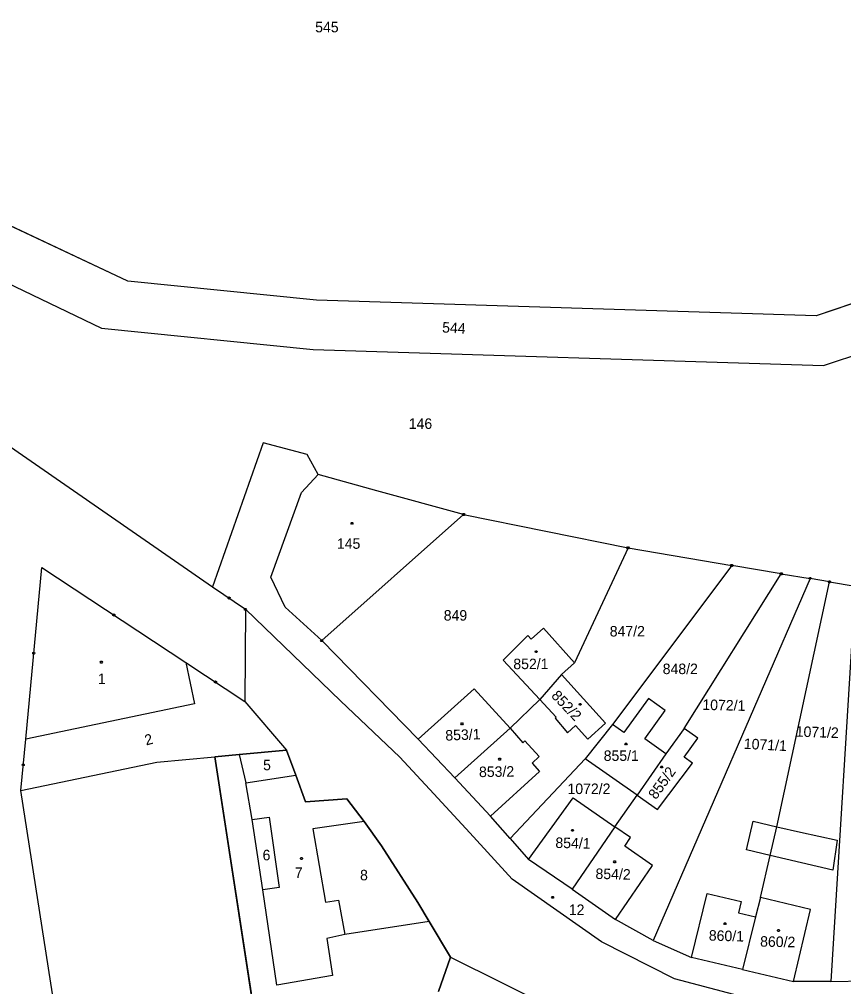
# Model space of a CAD drawing. Extents: x -841286 to -834997, y -1020681 to -1017810.
# Drawn here: x -838876.5 to -838743.2, y -1019133.5 to -1018977 of the extents above; entities that cross this region are included whole.
import ezdxf

# ---------------------------------------------------------------- set-up
doc = ezdxf.new("R2010")
doc.units = 0
for name, color, linetype in [('NERES_HRA', 7, 'Continuous'), ('OVNE_POP', 7, 'Continuous'), ('OVNE_PRE', 7, 'Continuous'), ('OVNE_SET', 7, 'Continuous'), ('OVNI_PRE', 7, 'Continuous'), ('OVNI_SET', 7, 'Continuous')]:
    doc.layers.add(name, color=color, linetype=linetype)

msp = doc.modelspace()

# ---------------------------------------------------------------- linework, layer by layer
at = {"layer": 'NERES_HRA'}
for points in [[(-838804.56, -1019056.95), (-838804.47, -1019057.1), (-838804.56, -1019057.25), (-838804.74, -1019057.25), (-838804.83, -1019057.1), (-838804.74, -1019056.95)], [(-838777.95, -1019062.36), (-838777.86, -1019062.51), (-838777.95, -1019062.66), (-838778.13, -1019062.66), (-838778.22, -1019062.51), (-838778.13, -1019062.36)], [(-838761.17, -1019065.2), (-838761.08, -1019065.35), (-838761.17, -1019065.5), (-838761.35, -1019065.5), (-838761.44, -1019065.35), (-838761.35, -1019065.2)], [(-838753.15, -1019066.57), (-838753.06, -1019066.72), (-838753.15, -1019066.87), (-838753.33, -1019066.87), (-838753.42, -1019066.72), (-838753.33, -1019066.57)], [(-838748.48, -1019067.3), (-838748.39, -1019067.45), (-838748.48, -1019067.6), (-838748.66, -1019067.6), (-838748.75, -1019067.45), (-838748.66, -1019067.3)], [(-838745.35, -1019067.86), (-838745.26, -1019068.01), (-838745.35, -1019068.16), (-838745.53, -1019068.16), (-838745.62, -1019068.01), (-838745.53, -1019067.86)], [(-838839.86, -1019072.3), (-838839.77, -1019072.45), (-838839.86, -1019072.6), (-838840.04, -1019072.6), (-838840.13, -1019072.45), (-838840.04, -1019072.3)], [(-838827.51, -1019077.37), (-838827.42, -1019077.52), (-838827.51, -1019077.67), (-838827.69, -1019077.67), (-838827.78, -1019077.52), (-838827.69, -1019077.37)]]:
    msp.add_lwpolyline(points, close=True, dxfattribs=at)
at = {"layer": 'OVNE_POP'}
for points in [[(-838822.6, -1019058.38), (-838822.51, -1019058.53), (-838822.6, -1019058.68), (-838822.78, -1019058.68), (-838822.87, -1019058.53), (-838822.78, -1019058.38)], [(-838863.18, -1019080.87), (-838863.09, -1019081.02), (-838863.18, -1019081.17), (-838863.36, -1019081.17), (-838863.45, -1019081.02), (-838863.36, -1019080.87)], [(-838790.14, -1019118.92), (-838790.05, -1019119.07), (-838790.14, -1019119.22), (-838790.32, -1019119.22), (-838790.41, -1019119.07), (-838790.32, -1019118.92)]]:
    msp.add_lwpolyline(points, close=True, dxfattribs=at)
at = {"layer": 'OVNE_SET'}
for p, q in [((-838859, -1019019.35), (-838948.75, -1018976.96)), ((-838944.44, -1018987.93), (-838863.24, -1019026.97)), ((-838702.3, -1019009.58), (-838747.6, -1019024.97)), ((-838828.44, -1019022.39), (-838859, -1019019.35)), ((-838746.4, -1019033.01), (-838707.91, -1019019.94)), ((-838747.6, -1019024.97), (-838828.44, -1019022.39)), ((-838908.59, -1019025.03), (-838845.25, -1019068.79)), ((-838863.24, -1019026.97), (-838828.96, -1019030.38)), ((-838828.96, -1019030.38), (-838746.4, -1019033.01)), ((-838837.08, -1019045.49), (-838845.25, -1019068.79)), ((-838829.97, -1019047.4), (-838837.08, -1019045.49)), ((-838828.2, -1019050.62), (-838829.97, -1019047.4)), ((-838830.87, -1019053.56), (-838828.2, -1019050.62)), ((-838818.69, -1019053.29), (-838828.2, -1019050.62)), ((-838835.82, -1019067.23), (-838830.87, -1019053.56)), ((-838804.65, -1019057.1), (-838818.69, -1019053.29)), ((-838827.6, -1019077.52), (-838804.65, -1019057.1)), ((-838804.65, -1019057.1), (-838778.04, -1019062.51)), ((-838778.04, -1019062.51), (-838786.71, -1019081.1)), ((-838778.04, -1019062.51), (-838761.26, -1019065.35)), ((-838761.26, -1019065.35), (-838780.53, -1019091.09)), ((-838753.24, -1019066.72), (-838761.26, -1019065.35)), ((-838875.5, -1019093.46), (-838872.88, -1019065.68)), ((-838872.88, -1019065.68), (-838849.58, -1019081.06)), ((-838768.98, -1019091.73), (-838753.24, -1019066.72)), ((-838753.24, -1019066.72), (-838748.57, -1019067.45)), ((-838833.52, -1019072.1), (-838835.82, -1019067.23)), ((-838748.57, -1019067.45), (-838773.97, -1019126.07)), ((-838753.96, -1019107.64), (-838745.44, -1019068.01)), ((-838745.44, -1019068.01), (-838748.57, -1019067.45)), ((-838745.44, -1019068.01), (-838741.31, -1019068.7)), ((-838741.31, -1019068.7), (-838745.21, -1019132.7)), ((-838845.25, -1019068.79), (-838839.95, -1019072.45)), ((-838839.95, -1019072.45), (-838840.03, -1019087.37)), ((-838824.54, -1019087.29), (-838839.95, -1019072.45)), ((-838827.6, -1019077.52), (-838833.52, -1019072.1)), ((-838791.73, -1019075.52), (-838793.69, -1019077.28)), ((-838786.71, -1019081.1), (-838791.73, -1019075.52)), ((-838812.01, -1019093.46), (-838827.6, -1019077.52)), ((-838798.27, -1019080.68), (-838794.24, -1019076.67)), ((-838793.69, -1019077.28), (-838794.24, -1019076.67)), ((-838849.58, -1019081.06), (-838840.03, -1019087.37)), ((-838849.58, -1019081.06), (-838848.18, -1019087.74)), ((-838792.32, -1019087.07), (-838798.27, -1019080.68)), ((-838788.81, -1019082.99), (-838786.71, -1019081.1)), ((-838788.81, -1019082.99), (-838792.32, -1019087.07)), ((-838781.7, -1019090.89), (-838788.81, -1019082.99)), ((-838812.01, -1019093.46), (-838802.95, -1019085.33)), ((-838802.95, -1019085.33), (-838797.11, -1019091.69)), ((-838840.03, -1019087.37), (-838833.28, -1019095.23)), ((-838814.95, -1019096.39), (-838824.54, -1019087.29)), ((-838792.32, -1019087.07), (-838797.11, -1019091.69)), ((-838792.32, -1019087.07), (-838789.65, -1019089.92)), ((-838774.73, -1019086.89), (-838778.71, -1019092.4)), ((-838772.04, -1019088.83), (-838774.73, -1019086.89)), ((-838848.18, -1019087.74), (-838875.5, -1019093.46)), ((-838775.34, -1019093.41), (-838772.04, -1019088.83)), ((-838789.65, -1019089.92), (-838789.82, -1019090.07)), ((-838789.82, -1019090.07), (-838787.84, -1019092.42)), ((-838797.11, -1019091.69), (-838806.06, -1019099.72)), ((-838797.11, -1019091.69), (-838795.08, -1019094.05)), ((-838787.84, -1019092.42), (-838786.54, -1019091.25)), ((-838786.54, -1019091.25), (-838784.55, -1019093.46)), ((-838780.53, -1019091.09), (-838784.96, -1019096.65)), ((-838784.55, -1019093.46), (-838781.7, -1019090.89)), ((-838778.71, -1019092.4), (-838780.53, -1019091.09)), ((-838768.98, -1019091.73), (-838771.95, -1019095.85)), ((-838766.76, -1019093.33), (-838768.98, -1019091.73)), ((-838876.29, -1019101.79), (-838875.5, -1019093.46)), ((-838806.06, -1019099.72), (-838812.01, -1019093.46)), ((-838795.08, -1019094.05), (-838794.75, -1019093.72)), ((-838794.75, -1019093.72), (-838792.43, -1019096.29)), ((-838771.95, -1019095.85), (-838775.34, -1019093.41)), ((-838768.96, -1019096.38), (-838766.76, -1019093.33)), ((-838840.98, -1019095.94), (-838833.28, -1019095.23)), ((-838833.28, -1019095.23), (-838831.81, -1019099.29)), ((-838854.28, -1019097.19), (-838844.9, -1019096.31)), ((-838844.9, -1019096.31), (-838840.98, -1019095.94)), ((-838838.17, -1019140.12), (-838844.9, -1019096.31)), ((-838840.98, -1019095.94), (-838839.9, -1019100.55)), ((-838809.46, -1019102.3), (-838814.95, -1019096.39)), ((-838784.96, -1019096.65), (-838797.11, -1019109.54)), ((-838792.43, -1019096.29), (-838793.57, -1019097.33)), ((-838776.54, -1019102.53), (-838784.96, -1019096.65)), ((-838771.95, -1019095.85), (-838776.54, -1019102.53)), ((-838767.59, -1019097.37), (-838768.96, -1019096.38)), ((-838876.29, -1019101.79), (-838854.28, -1019097.19)), ((-838793.57, -1019097.33), (-838792.35, -1019098.69)), ((-838773.29, -1019104.84), (-838767.59, -1019097.37)), ((-838839.9, -1019100.55), (-838831.81, -1019099.29)), ((-838831.81, -1019099.29), (-838830.25, -1019103.61)), ((-838800.32, -1019105.96), (-838806.06, -1019099.72)), ((-838792.35, -1019098.69), (-838800.32, -1019105.96)), ((-838838.87, -1019106.47), (-838839.9, -1019100.55)), ((-838862.62, -1019189.07), (-838876.29, -1019101.79)), ((-838830.25, -1019103.61), (-838823.55, -1019103.11)), ((-838823.55, -1019103.11), (-838820.76, -1019106.79)), ((-838803.62, -1019108.65), (-838809.46, -1019102.3)), ((-838794.14, -1019112.95), (-838786.9, -1019102.96)), ((-838786.9, -1019102.96), (-838780.17, -1019107.65)), ((-838780.17, -1019107.65), (-838776.54, -1019102.53)), ((-838776.54, -1019102.53), (-838773.29, -1019104.84)), ((-838838.87, -1019106.47), (-838836.12, -1019106.09)), ((-838836.12, -1019106.09), (-838834.48, -1019117.5)), ((-838797.11, -1019109.54), (-838800.32, -1019105.96)), ((-838837.11, -1019117.84), (-838838.87, -1019106.47)), ((-838820.76, -1019106.79), (-838829.03, -1019107.99)), ((-838820.76, -1019106.79), (-838817.92, -1019110.72)), ((-838780.17, -1019107.65), (-838787.08, -1019117.73)), ((-838777.66, -1019109.4), (-838780.17, -1019107.65)), ((-838755.04, -1019112.3), (-838753.96, -1019107.64)), ((-838829.03, -1019107.99), (-838826.98, -1019119.88)), ((-838796.77, -1019116.14), (-838803.62, -1019108.65)), ((-838778.54, -1019110.78), (-838777.66, -1019109.4)), ((-838817.92, -1019110.72), (-838812.07, -1019119.9)), ((-838797.11, -1019109.54), (-838794.14, -1019112.95)), ((-838774.06, -1019113.94), (-838778.54, -1019110.78)), ((-838756.62, -1019119.1), (-838755.04, -1019112.3)), ((-838787.08, -1019117.73), (-838794.14, -1019112.95)), ((-838780.08, -1019122.65), (-838774.06, -1019113.94)), ((-838782.36, -1019126.28), (-838796.77, -1019116.14)), ((-838834.48, -1019117.5), (-838837.11, -1019117.84)), ((-838834.87, -1019133.27), (-838837.11, -1019117.84)), ((-838787.08, -1019117.73), (-838780.08, -1019122.65)), ((-838767.77, -1019128.8), (-838765.26, -1019118.45)), ((-838765.26, -1019118.45), (-838759.72, -1019119.77)), ((-838826.98, -1019119.88), (-838824.91, -1019119.53)), ((-838824.91, -1019119.53), (-838823.84, -1019125.11)), ((-838812.07, -1019119.9), (-838810.21, -1019123.01)), ((-838759.72, -1019119.77), (-838760.15, -1019121.57)), ((-838756.62, -1019119.1), (-838757.41, -1019122.23)), ((-838748.51, -1019121.03), (-838756.62, -1019119.1)), ((-838760.15, -1019121.57), (-838757.41, -1019122.23)), ((-838751.28, -1019132.69), (-838748.51, -1019121.03)), ((-838810.21, -1019123.01), (-838823.84, -1019125.11)), ((-838810.21, -1019123.01), (-838806.77, -1019128.77)), ((-838773.97, -1019126.07), (-838780.08, -1019122.65)), ((-838757.41, -1019122.23), (-838759.52, -1019130.74)), ((-838823.84, -1019125.11), (-838826.8, -1019125.73)), ((-838826.8, -1019125.73), (-838825.88, -1019131.72)), ((-838770.54, -1019132.25), (-838782.36, -1019126.28)), ((-838773.97, -1019126.07), (-838767.77, -1019128.8)), ((-838806.77, -1019128.77), (-838808.73, -1019134.31)), ((-838806.77, -1019128.77), (-838770.31, -1019146.82)), ((-838759.52, -1019130.74), (-838767.77, -1019128.8)), ((-838759.52, -1019130.74), (-838751.28, -1019132.69)), ((-838825.88, -1019131.72), (-838834.87, -1019133.27)), ((-838760.9, -1019134.8), (-838770.54, -1019132.25)), ((-838745.21, -1019132.7), (-838751.28, -1019132.69)), ((-838745.21, -1019132.7), (-838739.12, -1019132.55))]:
    msp.add_line(p, q, dxfattribs=at)
for points in [[(-838842.44, -1019070.55), (-838842.45, -1019070.72), (-838842.61, -1019070.79), (-838842.76, -1019070.69), (-838842.75, -1019070.52), (-838842.59, -1019070.45)], [(-838861.07, -1019073.29), (-838861.08, -1019073.47), (-838861.24, -1019073.54), (-838861.39, -1019073.45), (-838861.38, -1019073.27), (-838861.22, -1019073.2)], [(-838874.33, -1019079.47), (-838874.17, -1019079.39), (-838874.03, -1019079.49), (-838874.05, -1019079.67), (-838874.21, -1019079.75), (-838874.35, -1019079.65)], [(-838844.65, -1019084.14), (-838844.65, -1019084.31), (-838844.81, -1019084.39), (-838844.96, -1019084.29), (-838844.96, -1019084.12), (-838844.8, -1019084.04)], [(-838876.04, -1019097.52), (-838875.88, -1019097.45), (-838875.74, -1019097.55), (-838875.75, -1019097.73), (-838875.91, -1019097.8), (-838876.05, -1019097.7)]]:
    msp.add_lwpolyline(points, close=True, dxfattribs=at)
at = {"layer": 'OVNI_PRE'}
for points in [[(-838792.82, -1019079.15), (-838792.73, -1019079.3), (-838792.82, -1019079.45), (-838793, -1019079.45), (-838793.09, -1019079.3), (-838793, -1019079.15)], [(-838785.7, -1019087.68), (-838785.61, -1019087.83), (-838785.7, -1019087.98), (-838785.88, -1019087.98), (-838785.97, -1019087.83), (-838785.88, -1019087.68)], [(-838804.81, -1019090.84), (-838804.72, -1019090.99), (-838804.81, -1019091.14), (-838804.99, -1019091.14), (-838805.08, -1019090.99), (-838804.99, -1019090.84)], [(-838778.28, -1019094.1), (-838778.19, -1019094.25), (-838778.28, -1019094.4), (-838778.46, -1019094.4), (-838778.55, -1019094.25), (-838778.46, -1019094.1)], [(-838798.71, -1019096.56), (-838798.62, -1019096.71), (-838798.71, -1019096.86), (-838798.89, -1019096.86), (-838798.98, -1019096.71), (-838798.89, -1019096.56)], [(-838772.52, -1019097.82), (-838772.43, -1019097.97), (-838772.52, -1019098.12), (-838772.7, -1019098.12), (-838772.79, -1019097.97), (-838772.7, -1019097.82)], [(-838786.94, -1019108.07), (-838786.85, -1019108.22), (-838786.94, -1019108.37), (-838787.12, -1019108.37), (-838787.21, -1019108.22), (-838787.12, -1019108.07)], [(-838830.78, -1019112.63), (-838830.69, -1019112.78), (-838830.78, -1019112.93), (-838830.96, -1019112.93), (-838831.05, -1019112.78), (-838830.96, -1019112.63)], [(-838780.1, -1019113.19), (-838780.01, -1019113.34), (-838780.1, -1019113.49), (-838780.28, -1019113.49), (-838780.37, -1019113.34), (-838780.28, -1019113.19)], [(-838762.27, -1019123.18), (-838762.18, -1019123.33), (-838762.27, -1019123.48), (-838762.45, -1019123.48), (-838762.54, -1019123.33), (-838762.45, -1019123.18)], [(-838753.6, -1019124.3), (-838753.51, -1019124.45), (-838753.6, -1019124.6), (-838753.78, -1019124.6), (-838753.87, -1019124.45), (-838753.78, -1019124.3)]]:
    msp.add_lwpolyline(points, close=True, dxfattribs=at)
at = {"layer": 'OVNI_SET'}
for p, q in [((-838758.88, -1019111.37), (-838757.78, -1019106.74)), ((-838757.78, -1019106.74), (-838753.96, -1019107.64)), ((-838753.96, -1019107.64), (-838750.15, -1019108.54)), ((-838750.15, -1019108.54), (-838744.2, -1019109.8)), ((-838744.2, -1019109.8), (-838744.9, -1019114.65)), ((-838755.04, -1019112.3), (-838758.88, -1019111.37)), ((-838744.9, -1019114.65), (-838755.04, -1019112.3))]:
    msp.add_line(p, q, dxfattribs=at)
for points in [[(-838702.3, -1019009.58), (-838747.6, -1019024.97), (-838828.44, -1019022.39), (-838859, -1019019.35), (-838948.75, -1018976.96), (-838956.29, -1018978.9), (-838962.1, -1018986.94)], [(-838808.73, -1019134.31), (-838806.77, -1019128.77), (-838810.21, -1019123.01), (-838812.07, -1019119.9), (-838817.92, -1019110.72), (-838820.76, -1019106.79), (-838823.55, -1019103.11), (-838830.25, -1019103.61), (-838831.81, -1019099.29), (-838833.28, -1019095.23), (-838840.98, -1019095.94), (-838844.9, -1019096.31), (-838838.17, -1019140.12), (-838822.57, -1019164.73)]]:
    msp.add_lwpolyline(points, dxfattribs=at)

# ---------------------------------------------------------------- texts
at = {"layer": 'OVNE_PRE'}
for s, p in [('545', (-838828.66, -1018979.06)), ('146', (-838813.52, -1019043.25)), ('145', (-838825.14, -1019062.66)), ('849', (-838807.86, -1019074.28)), ('847/2', (-838781, -1019076.85)), ('852/1', (-838796.6, -1019082.14)), ('848/2', (-838772.43, -1019082.94)), ('1', (-838863.83, -1019084.55)), ('855/1', (-838781.98, -1019096.99)), ('5', (-838837.09, -1019098.5)), ('1072/2', (-838787.84, -1019102.35)), ('6', (-838837.17, -1019113.08)), ('7', (-838831.96, -1019115.94)), ('8', (-838821.4, -1019116.32)), ('12', (-838787.62, -1019121.93))]:
    msp.add_text(s, height=1.7, dxfattribs=at).set_placement(p)
for s, rotation, p in [('544', 356.9527, (-838808.15, -1019027.64)), ('852/2', 313.8663, (-838790.57, -1019086.55)), ('1072/1', 358.4997, (-838766.03, -1019088.72)), ('853/1', 2.2345, (-838807.57, -1019093.71)), ('1071/2', 358.0986, (-838750.93, -1019093.06)), ('2', 14.9542, (-838856, -1019094.5)), ('1071/1', 356.9527, (-838759.34, -1019095.03)), ('853/2', 0.9167, (-838802.14, -1019099.62)), ('855/2', 54.431, (-838773.52, -1019103.35)), ('854/1', 358.6143, (-838789.81, -1019111.07)), ('854/2', 358.6716, (-838783.32, -1019116.09)), ('860/1', 358.3278, (-838764.99, -1019126.07)), ('860/2', 358.8435, (-838756.68, -1019127.05))]:
    msp.add_text(s, height=1.7, rotation=rotation, dxfattribs=at).set_placement(p)

doc.saveas('drawing.dxf')
